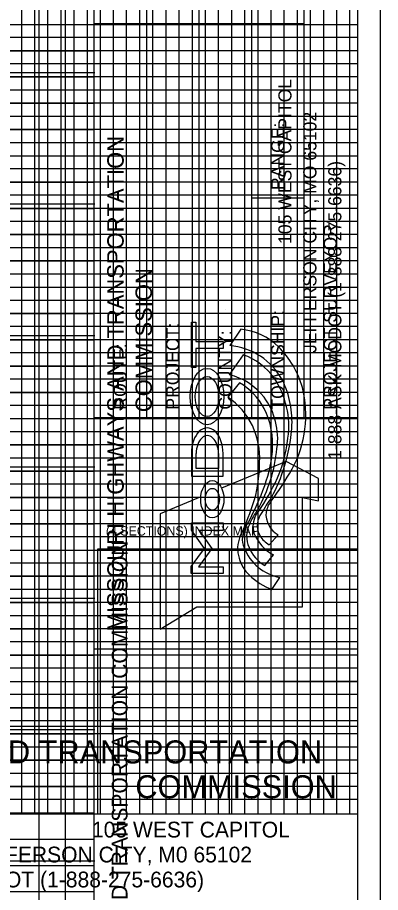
# Model space of a CAD drawing. Extents: x 0 to 31.6, y 0 to 20.8.
# Drawn here: x 28.84 to 31.6, y 3.61 to 10.27 of the extents above; entities that cross this region are included whole.
import ezdxf

# ---------------------------------------------------------------- set-up
doc = ezdxf.new("R2010")
doc.units = 0
for name, color, linetype in [('Border-Border', 7, 'Continuous'), ('Border-Bridge survey map', 7, 'Continuous'), ('Border-Bridge survey title block', 7, 'Continuous'), ('Border-Bridge xsection major grid lines', 7, 'Continuous'), ('Border-Bridge xsection minor grid lines', 7, 'Continuous'), ('Border-Full profile major grid lines', 7, 'Continuous'), ('Border-Full xsection major grid lines', 7, 'Continuous'), ('Border-Full xsection minor grid lines', 7, 'Continuous'), ('Border-Plan-profile major grid lines', 7, 'Continuous'), ('Border-Plotting block', 7, 'Continuous'), ('Border-Title block - Final Plans Consultant Manual Seal', 7, 'Continuous'), ('Border-Title block - Final Plans Electronic Seal', 7, 'Continuous'), ('Border-Title block - Location Survey Electronic Seal', 7, 'Continuous'), ('Border-Title block - Standard Plans Electronic Seal', 7, 'Continuous'), ('Border-Xsection shape', 7, 'Continuous')]:
    doc.layers.add(name, color=color, linetype=linetype)

msp = doc.modelspace()

# ---------------------------------------------------------------- linework, layer by layer
at = {"layer": 'Border-Border'}
msp.add_line((31.425, 20.5875), (31.425, 0.2125), dxfattribs=at)
at = {"layer": 'Border-Bridge survey map'}
for p, q in [((30.4469, 6.2219), (30.4469, 4.2046)), ((29.4469, 5.2141), (31.4249, 5.2141))]:
    msp.add_line(p, q, dxfattribs=at)
msp.add_lwpolyline([(29.4469, 4.2046), (29.4469, 6.2219), (31.4249, 6.2219)], dxfattribs=at)
at = {"layer": 'Border-Bridge survey title block'}
msp.add_lwpolyline([(26.9414, 0.2125), (26.9414, 4.2047), (31.4249, 4.2047)], dxfattribs=at)
at = {"layer": 'Border-Bridge xsection major grid lines'}
for p, q in [((29.6649, 4.2046), (29.6649, 20.5875)), ((30.6649, 20.5875), (30.6649, 4.2046)), ((0.175, 10.2125), (31.4249, 10.2125)), ((0.175, 9.2125), (31.4249, 9.2125)), ((0.175, 8.2125), (31.4249, 8.2125)), ((0.175, 7.2125), (31.4249, 7.2125)), ((0.175, 6.2125), (31.4249, 6.2125)), ((0.175, 5.2125), (31.4249, 5.2125))]:
    msp.add_line(p, q, dxfattribs=at)
at = {"layer": 'Border-Bridge xsection minor grid lines'}
for p, q in [((28.8649, 20.5875), (28.8649, 4.2046)), ((28.9649, 20.5875), (28.9649, 4.2046)), ((29.0649, 20.5875), (29.0649, 4.2046)), ((29.1649, 20.5875), (29.1649, 4.2046)), ((29.2649, 20.5875), (29.2649, 4.2046)), ((29.3649, 20.5875), (29.3649, 4.2046)), ((29.4649, 20.5875), (29.4649, 4.2046)), ((29.5649, 20.5875), (29.5649, 4.2046)), ((29.7649, 20.5875), (29.7649, 4.2046)), ((29.8649, 20.5875), (29.8649, 4.2046)), ((29.9649, 20.5875), (29.9649, 4.2046)), ((30.0649, 20.5875), (30.0649, 4.2046)), ((30.1649, 20.5875), (30.1649, 4.2046)), ((30.2649, 20.5875), (30.2649, 4.2046)), ((30.3649, 20.5875), (30.3649, 4.2046)), ((30.4649, 20.5875), (30.4649, 4.2046)), ((30.5649, 20.5875), (30.5649, 4.2046)), ((30.7649, 20.5875), (30.7649, 4.2046)), ((30.8649, 20.5875), (30.8649, 4.2046)), ((30.9649, 20.5875), (30.9649, 4.2046)), ((31.0649, 20.5875), (31.0649, 4.2046)), ((31.1649, 20.5875), (31.1649, 4.2046)), ((31.2649, 20.5875), (31.2649, 4.2046)), ((31.3649, 20.5875), (31.3649, 4.2046)), ((31.4249, 10.1125), (0.175, 10.1125)), ((31.4249, 10.0125), (0.175, 10.0125)), ((31.4249, 9.9125), (0.175, 9.9125)), ((31.4249, 9.8125), (0.175, 9.8125)), ((31.4249, 9.7125), (0.175, 9.7125)), ((31.4249, 9.6125), (0.175, 9.6125)), ((31.4249, 9.5125), (0.175, 9.5125)), ((31.4249, 9.4125), (0.175, 9.4125)), ((31.4249, 9.3125), (0.175, 9.3125)), ((31.4249, 9.1125), (0.175, 9.1125)), ((31.4249, 9.0125), (0.175, 9.0125)), ((31.4249, 8.9125), (0.175, 8.9125)), ((31.4249, 8.8125), (0.175, 8.8125)), ((31.4249, 8.7125), (0.175, 8.7125)), ((31.4249, 8.6125), (0.175, 8.6125)), ((31.4249, 8.5125), (0.175, 8.5125)), ((31.4249, 8.4125), (0.175, 8.4125)), ((31.4249, 8.3125), (0.175, 8.3125)), ((31.4249, 8.1125), (0.175, 8.1125)), ((31.4249, 8.0125), (0.175, 8.0125)), ((31.4249, 7.9125), (0.175, 7.9125)), ((31.4249, 7.8125), (0.175, 7.8125)), ((31.4249, 7.7125), (0.175, 7.7125)), ((31.4249, 7.6125), (0.175, 7.6125)), ((31.4249, 7.5125), (0.175, 7.5125)), ((31.4249, 7.4125), (0.175, 7.4125)), ((31.4249, 7.3125), (0.175, 7.3125)), ((31.4249, 7.1125), (0.175, 7.1125)), ((31.4249, 7.0125), (0.175, 7.0125)), ((31.4249, 6.9125), (0.175, 6.9125)), ((31.4249, 6.8125), (0.175, 6.8125)), ((31.4249, 6.7125), (0.175, 6.7125)), ((31.4249, 6.6125), (0.175, 6.6125)), ((31.4249, 6.5125), (0.175, 6.5125)), ((31.4249, 6.4125), (0.175, 6.4125)), ((31.4249, 6.3125), (0.175, 6.3125)), ((31.4249, 6.1125), (0.175, 6.1125)), ((31.4249, 6.0125), (0.175, 6.0125)), ((31.4249, 5.9125), (0.175, 5.9125)), ((31.4249, 5.8125), (0.175, 5.8125)), ((31.4249, 5.7125), (0.175, 5.7125)), ((31.4249, 5.6125), (0.175, 5.6125)), ((31.4249, 5.5125), (0.175, 5.5125)), ((31.4249, 5.4125), (0.175, 5.4125)), ((31.4249, 5.3125), (0.175, 5.3125)), ((31.4249, 5.1125), (0.175, 5.1125)), ((31.4249, 5.0125), (0.175, 5.0125)), ((31.4249, 4.9125), (0.175, 4.9125)), ((31.4249, 4.8125), (0.175, 4.8125)), ((31.4249, 4.7125), (0.175, 4.7125)), ((31.4249, 4.6125), (0.175, 4.6125)), ((31.4249, 4.5125), (0.175, 4.5125)), ((31.4249, 4.4125), (0.175, 4.4125)), ((31.4249, 4.3125), (0.175, 4.3125))]:
    msp.add_line(p, q, dxfattribs=at)
at = {"layer": 'Border-Full profile major grid lines'}
for p, q in [((29.4171, 9.8436), (0.175, 9.8436)), ((29.4171, 8.8436), (0.175, 8.8436)), ((29.4171, 7.8436), (0.175, 7.8436)), ((29.4171, 6.8436), (0.175, 6.8436)), ((29.4171, 5.8436), (0.175, 5.8436)), ((29.4171, 4.8436), (0.175, 4.8436)), ((29.4171, 3.8436), (0.175, 3.8436))]:
    msp.add_line(p, q, dxfattribs=at)
at = {"layer": 'Border-Full xsection major grid lines'}
for p, q in [((0.175, 10.2125), (29.4171, 10.2125)), ((0.175, 9.2125), (29.4171, 9.2125)), ((0.175, 8.2125), (29.4171, 8.2125)), ((0.175, 7.2125), (29.4171, 7.2125)), ((0.175, 6.2125), (29.4171, 6.2125)), ((0.175, 5.2125), (29.4171, 5.2125)), ((0.175, 4.2125), (29.4171, 4.2125)), ((31.4249, 4.2125), (31.4254, 4.2125))]:
    msp.add_line(p, q, dxfattribs=at)
at = {"layer": 'Border-Full xsection minor grid lines'}
for p, q in [((28.9999, 0.2125), (28.9999, 20.5875)), ((29.1999, 0.2125), (29.1999, 20.5875)), ((0.175, 10.0125), (29.4171, 10.0125)), ((0.175, 9.8125), (29.4171, 9.8125)), ((0.175, 9.6125), (29.4171, 9.6125)), ((0.175, 9.4125), (29.4171, 9.4125)), ((0.175, 9.0125), (29.4171, 9.0125)), ((0.175, 8.8125), (29.4171, 8.8125)), ((0.175, 8.6125), (29.4171, 8.6125)), ((0.175, 8.4125), (29.4171, 8.4125)), ((0.175, 8.0125), (29.4171, 8.0125)), ((0.175, 7.8125), (29.4171, 7.8125)), ((0.175, 7.6125), (29.4171, 7.6125)), ((0.175, 7.4125), (29.4171, 7.4125)), ((0.175, 7.0125), (29.4171, 7.0125)), ((0.175, 6.8125), (29.4171, 6.8125)), ((0.175, 6.6125), (29.4171, 6.6125)), ((0.175, 6.4125), (29.4171, 6.4125)), ((0.175, 6.0125), (29.4171, 6.0125)), ((0.175, 5.8125), (29.4171, 5.8125)), ((0.175, 5.6125), (29.4171, 5.6125)), ((0.175, 5.4125), (29.4171, 5.4125)), ((0.175, 5.0125), (29.4171, 5.0125)), ((0.175, 4.8125), (29.4171, 4.8125)), ((0.175, 4.6125), (29.4171, 4.6125)), ((0.175, 4.4125), (29.4171, 4.4125)), ((31.4249, 4.4125), (31.4254, 4.4125)), ((0.175, 4.0125), (29.4171, 4.0125)), ((0.175, 3.8125), (29.4171, 3.8125)), ((0.175, 3.6125), (29.4171, 3.6125))]:
    msp.add_line(p, q, dxfattribs=at)
at = {"layer": 'Border-Plan-profile major grid lines'}
for p, q in [((29.4233, 9.8436), (0.1811, 9.8436)), ((29.4233, 8.8436), (0.1811, 8.8436)), ((29.4233, 7.8436), (0.1811, 7.8436)), ((29.4233, 6.8436), (0.1811, 6.8436)), ((29.4233, 5.8436), (0.1811, 5.8436)), ((29.4233, 4.8436), (0.1811, 4.8436)), ((29.4233, 3.8436), (0.1811, 3.8436))]:
    msp.add_line(p, q, dxfattribs=at)
at = {"layer": 'Border-Plotting block'}
msp.add_lwpolyline([(0, 0), (31.5999, 0), (31.5999, 20.8), (0, 20.8)], close=True, dxfattribs=at)
at = {"layer": 'Border-Title block - Final Plans Consultant Manual Seal'}
for p, q in [((29.4171, 20.5875), (29.4171, 0.2125)), ((30.5365, 7.8922), (30.4519, 7.768)), ((30.5541, 7.6979), (30.4483, 7.5468)), ((30.5272, 7.4859), (30.4378, 7.3747)), ((30.16, 6.9464), (30.16, 6.774)), ((30.1963, 6.8334), (30.1963, 6.9464)), ((30.3662, 6.9464), (30.3662, 6.8334)), ((30.4008, 6.774), (30.4008, 6.9464)), ((30.8803, 6.8869), (30.3903, 6.6831)), ((31.1267, 6.7566), (30.8803, 6.8869)), ((30.3662, 6.8334), (30.1963, 6.8334)), ((30.16, 6.774), (30.4008, 6.774)), ((31.1267, 6.5855), (31.1267, 6.7566)), ((30.2315, 6.617), (29.922, 6.4883)), ((31.0071, 5.7793), (31.0071, 6.6109)), ((31.0071, 6.6109), (31.1267, 6.5855)), ((29.922, 6.4883), (29.922, 5.6099)), ((30.7517, 6.2525), (30.821, 6.3285)), ((30.7188, 6.0943), (30.7857, 6.1748)), ((30.7729, 5.9114), (30.8329, 6.0039)), ((29.922, 5.6099), (30.2004, 5.7793)), ((30.2004, 5.7793), (31.0071, 5.7793)), ((29.4171, 5.4599), (31.425, 5.4599))]:
    msp.add_line(p, q, dxfattribs=at)
for points in [[(30.1599, 7.6015), (30.1599, 7.9459), (30.1934, 7.9459), (30.1934, 7.8005), (30.4008, 7.8005), (30.4008, 7.7459), (30.1934, 7.7459), (30.1934, 7.6015)], [(30.4008, 6.0337), (30.1592, 6.0337), (30.1592, 6.0882), (30.2588, 6.2251), (30.16, 6.3638), (30.16, 6.4193), (30.4008, 6.4193), (30.4008, 6.3619), (30.2185, 6.3619), (30.3164, 6.2251), (30.2147, 6.0844), (30.4008, 6.0844)]]:
    msp.add_lwpolyline(points, close=True, dxfattribs=at)
for centre, radius, start, end in [((30.4952, 7.4285), 0.4656, 45.16931, 84.90202), ((30.4076, 7.2631), 0.5069, 28.57249, 84.98895), ((30.3292, 7.2587), 0.7029, 15.82215, 45.3322), ((30.3947, 7.2387), 0.486, 35.48059, 70.84743), ((30.3361, 7.0832), 0.477, 37.82053, 76.39644), ((30.2447, 7.0264), 0.5393, 29.26655, 58.41911), ((30.2462, 7.1558), 0.6553, 351.92721, 33.85401), ((30.1918, 7.186), 0.7342, 356.25263, 25.80365), ((30.1706, 7.2409), 0.8608, 331.45894, 14.08516), ((30.1256, 6.9166), 0.5543, 55.72742, 55.72758), ((30.1256, 6.9166), 0.5543, 356.10332, 55.7272), ((30.2854, 7.0598), 0.5315, 351.87184, 36.46402), ((30.1519, 7.0155), 0.6267, 355.20478, 25.98369), ((29.6592, 7.2299), 1.2685, 339.27778, 355.84654), ((29.8531, 7.1765), 1.048, 334.30971, 353.82369), ((29.6238, 7.1031), 1.1937, 330.80189, 354.30584), ((29.6939, 7.068), 1.0875, 338.33661, 354.46616), ((29.6632, 6.8729), 1.0155, 341.46898, 0.34157), ((29.0087, 7.8983), 2.1957, 323.25469, 330.87553), ((30.017, 7.0594), 0.8742, 328.33342, 341.42803), ((28.6965, 7.4396), 2.1518, 330.82713, 338.94553), ((28.929, 7.6684), 2.0944, 325.33774, 333.14131), ((33.478, 4.796), 3.2616, 146.40943, 149.03928), ((28.5928, 7.2437), 2.1483, 334.37273, 341.16645), ((30.9123, 6.4645), 0.1877, 140.18798, 168.85058), ((31.1325, 6.1801), 0.5778, 143.87617, 156.87144), ((30.7955, 6.3922), 0.167, 149.40426, 197.76384), ((30.8136, 6.3982), 0.1526, 150.25518, 210.64132), ((30.9045, 6.4846), 0.177, 174.75269, 241.86614), ((30.7795, 6.3173), 0.1996, 153.27349, 205.14999), ((30.7203, 6.2966), 0.1729, 147.01991, 203.02392), ((30.9419, 6.465), 0.3295, 202.06293, 241.72012), ((30.7493, 6.2245), 0.2373, 157.70916, 198.17281), ((30.8522, 6.4245), 0.1993, 211.49535, 239.68972), ((30.9032, 6.3653), 0.3681, 201.72885, 258.99607), ((30.8578, 6.3362), 0.279, 201.81038, 240.11136), ((30.7878, 6.2214), 0.2733, 195.0361, 226.99124), ((30.9511, 6.3774), 0.4989, 225.49883, 249.07866)]:
    msp.add_arc(centre, radius, start, end, dxfattribs=at)
for centre, major_axis, ratio in [((30.2788, 7.3805), (0, 0.2144), 0.595517), ((30.2788, 7.3804), (0, -0.153), 0.589579), ((30.3191, 6.5992), (0, 0.1416), 0.623747), ((30.3191, 6.5992), (0, 0.0823), 0.65252)]:
    msp.add_ellipse(centre, major_axis=major_axis, ratio=ratio, dxfattribs=at)
for centre, major_axis, ratio in [((30.2803, 6.9463), (0, -0.1961), 0.614143), ((30.2812, 6.9463), (0, -0.1368), 0.62091)]:
    msp.add_ellipse(centre, major_axis=major_axis, ratio=ratio, start_param=1.570796, end_param=4.712389, dxfattribs=at)
at = {"layer": 'Border-Title block - Final Plans Electronic Seal'}
for p, q in [((29.4171, 20.5875), (29.4171, 0.2125)), ((30.5365, 7.8922), (30.4519, 7.768)), ((30.5541, 7.6979), (30.4483, 7.5468)), ((30.5272, 7.4859), (30.4378, 7.3747)), ((30.16, 6.9464), (30.16, 6.774)), ((30.1963, 6.8334), (30.1963, 6.9464)), ((30.3662, 6.9464), (30.3662, 6.8334)), ((30.4008, 6.774), (30.4008, 6.9464)), ((30.8803, 6.8869), (30.3903, 6.6831)), ((31.1267, 6.7566), (30.8803, 6.8869)), ((30.3662, 6.8334), (30.1963, 6.8334)), ((30.16, 6.774), (30.4008, 6.774)), ((31.1267, 6.5855), (31.1267, 6.7566)), ((30.2315, 6.617), (29.922, 6.4883)), ((31.0071, 5.7793), (31.0071, 6.6109)), ((31.0071, 6.6109), (31.1267, 6.5855)), ((29.922, 6.4883), (29.922, 5.6099)), ((30.7517, 6.2525), (30.821, 6.3285)), ((30.7188, 6.0943), (30.7857, 6.1748)), ((30.7729, 5.9114), (30.8329, 6.0039)), ((29.922, 5.6099), (30.2004, 5.7793)), ((30.2004, 5.7793), (31.0071, 5.7793)), ((29.4171, 5.4599), (31.425, 5.4599))]:
    msp.add_line(p, q, dxfattribs=at)
for points in [[(30.1599, 7.6015), (30.1599, 7.9459), (30.1934, 7.9459), (30.1934, 7.8005), (30.4008, 7.8005), (30.4008, 7.7459), (30.1934, 7.7459), (30.1934, 7.6015)], [(30.4008, 6.0337), (30.1592, 6.0337), (30.1592, 6.0882), (30.2588, 6.2251), (30.16, 6.3638), (30.16, 6.4193), (30.4008, 6.4193), (30.4008, 6.3619), (30.2185, 6.3619), (30.3164, 6.2251), (30.2147, 6.0844), (30.4008, 6.0844)]]:
    msp.add_lwpolyline(points, close=True, dxfattribs=at)
for centre, radius, start, end in [((30.4952, 7.4285), 0.4656, 45.16931, 84.90202), ((30.4076, 7.2631), 0.5069, 28.57249, 84.98895), ((30.3292, 7.2587), 0.7029, 15.82215, 45.3322), ((30.3947, 7.2387), 0.486, 35.48059, 70.84743), ((30.3361, 7.0832), 0.477, 37.82053, 76.39644), ((30.2447, 7.0264), 0.5393, 29.26655, 58.41911), ((30.2462, 7.1558), 0.6553, 351.92721, 33.85401), ((30.1918, 7.186), 0.7342, 356.25263, 25.80365), ((30.1706, 7.2409), 0.8608, 331.45894, 14.08516), ((30.1256, 6.9166), 0.5543, 55.72742, 55.72758), ((30.1256, 6.9166), 0.5543, 356.10332, 55.7272), ((30.2854, 7.0598), 0.5315, 351.87184, 36.46402), ((30.1519, 7.0155), 0.6267, 355.20478, 25.98369), ((29.6592, 7.2299), 1.2685, 339.27778, 355.84654), ((29.8531, 7.1765), 1.048, 334.30971, 353.82369), ((29.6238, 7.1031), 1.1937, 330.80189, 354.30584), ((29.6939, 7.068), 1.0875, 338.33661, 354.46616), ((29.6632, 6.8729), 1.0155, 341.46898, 0.34157), ((29.0087, 7.8983), 2.1957, 323.25469, 330.87553), ((30.017, 7.0594), 0.8742, 328.33342, 341.42803), ((28.6965, 7.4396), 2.1518, 330.82713, 338.94553), ((28.929, 7.6684), 2.0944, 325.33774, 333.14131), ((33.478, 4.796), 3.2616, 146.40943, 149.03928), ((28.5928, 7.2437), 2.1483, 334.37273, 341.16645), ((30.9123, 6.4645), 0.1877, 140.18798, 168.85058), ((31.1325, 6.1801), 0.5778, 143.87617, 156.87144), ((30.7955, 6.3922), 0.167, 149.40426, 197.76384), ((30.8136, 6.3982), 0.1526, 150.25518, 210.64132), ((30.9045, 6.4846), 0.177, 174.75269, 241.86614), ((30.7795, 6.3173), 0.1996, 153.27349, 205.14999), ((30.7203, 6.2966), 0.1729, 147.01991, 203.02392), ((30.9419, 6.465), 0.3295, 202.06293, 241.72012), ((30.7493, 6.2245), 0.2373, 157.70916, 198.17281), ((30.8522, 6.4245), 0.1993, 211.49535, 239.68972), ((30.9032, 6.3653), 0.3681, 201.72885, 258.99607), ((30.8578, 6.3362), 0.279, 201.81038, 240.11136), ((30.7878, 6.2214), 0.2733, 195.0361, 226.99124), ((30.9511, 6.3774), 0.4989, 225.49883, 249.07866)]:
    msp.add_arc(centre, radius, start, end, dxfattribs=at)
for centre, major_axis, ratio in [((30.2788, 7.3805), (0, 0.2144), 0.595517), ((30.2788, 7.3804), (0, -0.153), 0.589579), ((30.3191, 6.5992), (0, 0.1416), 0.623747), ((30.3191, 6.5992), (0, 0.0823), 0.65252)]:
    msp.add_ellipse(centre, major_axis=major_axis, ratio=ratio, dxfattribs=at)
for centre, major_axis, ratio in [((30.2803, 6.9463), (0, -0.1961), 0.614143), ((30.2812, 6.9463), (0, -0.1368), 0.62091)]:
    msp.add_ellipse(centre, major_axis=major_axis, ratio=ratio, start_param=1.570796, end_param=4.712389, dxfattribs=at)
at = {"layer": 'Border-Title block - Location Survey Electronic Seal'}
for p, q in [((29.4171, 20.5875), (29.4171, 0.2125)), ((29.8171, 13.2202), (29.8171, 7.2202)), ((30.2171, 13.2202), (30.2171, 7.2202)), ((30.6171, 13.2202), (30.6171, 7.2202)), ((31.0171, 13.2202), (31.0171, 7.2202)), ((29.4171, 10.2202), (31.0171, 10.2202)), ((30.8117, 9.6142), (30.8117, 9.6142)), ((31.2171, 9.0806), (31.2171, 9.0806)), ((30.6171, 8.8921), (31.0171, 8.8921)), ((30.8171, 8.2648), (30.8171, 8.2648)), ((30.8171, 8.2648), (30.8171, 8.2648)), ((30.0171, 8.115), (30.0171, 8.115)), ((30.4229, 8.0446), (30.4229, 8.0446)), ((29.6171, 7.9411), (29.6171, 7.9411)), ((29.4171, 7.2202), (31.425, 7.2202))]:
    msp.add_line(p, q, dxfattribs=at)
at = {"layer": 'Border-Title block - Standard Plans Electronic Seal'}
msp.add_line((23.4249, 4.8718), (31.425, 4.8718), dxfattribs=at)
at = {"layer": 'Border-Xsection shape'}
msp.add_lwpolyline([(29.4171, 0.2125), (0.175, 0.2125), (0.175, 20.5875), (29.4171, 20.5875)], close=True, dxfattribs=at)

# ---------------------------------------------------------------- texts
at = {"layer": 'Border-Bridge survey map'}
msp.add_text('(4 SECTIONS) INDEX MAP', height=0.070563, dxfattribs=at).set_placement((29.5084, 6.3227))
at = {"layer": 'Border-Title block - Final Plans Consultant Manual Seal'}
for s, height, p in [('105 WEST CAPITOL', 0.1, (30.922, 8.542)), ('JEFFERSON CITY, MO 65102', 0.1, (31.112, 7.712)), ('MISSOURI HIGHWAYS AND TRANSPORTATION', 0.125, (29.6442, 5.5933)), ('1-888-ASK-MODOT (1-888-275-6636)', 0.1, (31.302, 6.8991)), ('COMMISSION', 0.125, (29.8592, 7.2617))]:
    msp.add_text(s, height=height, rotation=90, dxfattribs=at).set_placement(p)
at = {"layer": 'Border-Title block - Final Plans Electronic Seal'}
for s, height, p in [('105 WEST CAPITOL', 0.1, (30.922, 8.542)), ('JEFFERSON CITY, MO 65102', 0.1, (31.112, 7.712)), ('MISSOURI HIGHWAYS AND TRANSPORTATION', 0.125, (29.6442, 5.5933)), ('1-888-ASK-MODOT (1-888-275-6636)', 0.1, (31.302, 6.8991)), ('COMMISSION', 0.125, (29.8592, 7.2617))]:
    msp.add_text(s, height=height, rotation=90, dxfattribs=at).set_placement(p)
at = {"layer": 'Border-Title block - Location Survey Electronic Seal'}
for s, height, p in [('RANGE:', 0.1, (30.8671, 8.9528)), ('PROJECT SURVEYOR:', 0.1, (31.2671, 7.281)), ('TOWNSHIP:', 0.1, (30.8671, 7.281)), ('PROJECT:', 0.1, (30.0671, 7.281)), ('COUNTY:', 0.1, (30.4671, 7.281)), ('ROUTE:', 0.1, (29.6671, 7.281)), ('SURVEY FOR: MISSOURI HIGHWAYS AND TRANSPORTATION COMMISSION', 0.12, (29.6734, 0.4356))]:
    msp.add_text(s, height=height, rotation=90, dxfattribs=at).set_placement(p)
at = {"layer": 'Border-Title block - Standard Plans Electronic Seal'}
for s, height, p in [('MISSOURI HIGHWAYS AND TRANSPORTATION', 0.175, (25.8764, 4.5883)), ('COMMISSION', 0.175, (29.733, 4.3233)), ('105 WEST CAPITOL', 0.12, (29.4026, 4.0246)), ('JEFFERSON CITY, M0 65102', 0.12, (28.4547, 3.8346)), ('1-888-ASK-MODOT (1-888-275-6636)', 0.12, (27.5272, 3.6446))]:
    msp.add_text(s, height=height, dxfattribs=at).set_placement(p)

doc.saveas('drawing.dxf')
